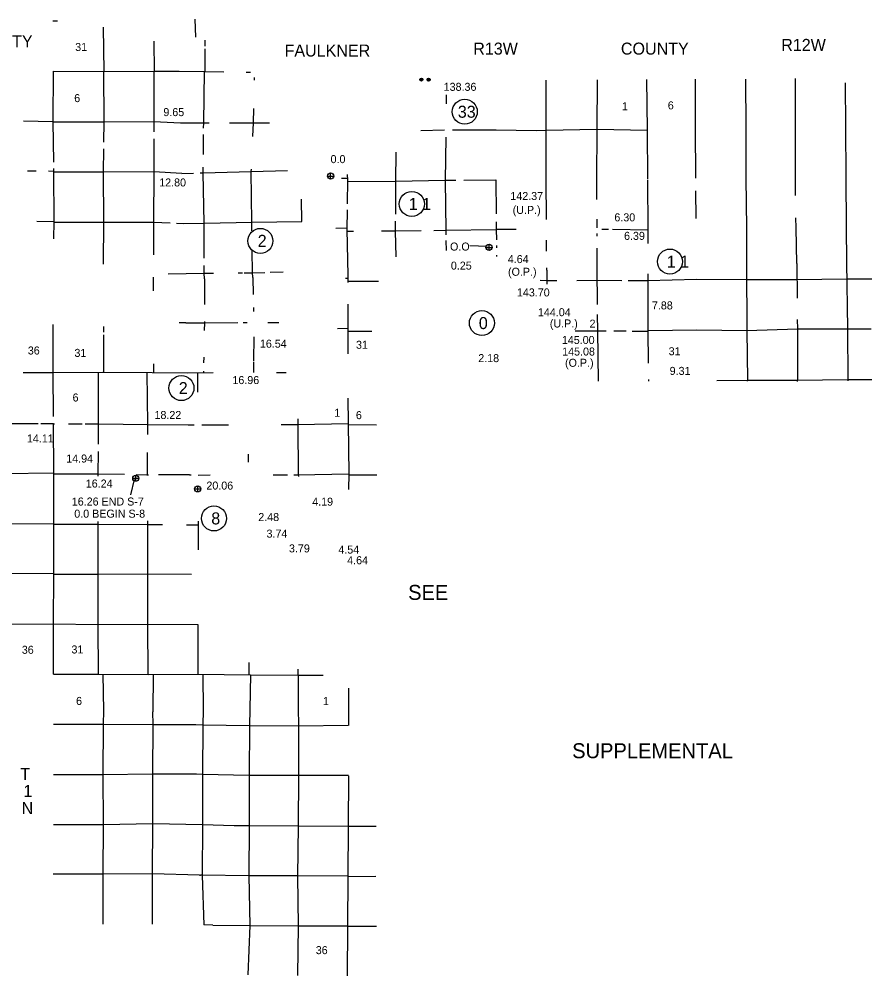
# Model space of a CAD drawing. Extents: x 1127717 to 1741049, y 2026793 to 2244711.
# Drawn here: x 1147166 to 1169656, y 2120572 to 2145808 of the extents above; entities that cross this region are included whole.
import ezdxf

# ---------------------------------------------------------------- set-up
doc = ezdxf.new("R2010")
doc.units = 0
for name, color, linetype in [('25', 7, 'Continuous'), ('26', 7, 'Continuous'), ('27', 7, 'Continuous'), ('30', 7, 'Continuous'), ('4', 7, 'Continuous'), ('5', 7, 'Continuous'), ('58', 7, 'Continuous')]:
    doc.layers.add(name, color=color, linetype=linetype)

msp = doc.modelspace()

# ---------------------------------------------------------------- linework, layer by layer
at = {"layer": '25'}
for p, q in [((1159050, 2139833), (1159511, 2139820)), ((1150109, 2133259), (1150210, 2133664))]:
    msp.add_line(p, q, dxfattribs=at)
at = {"layer": '26'}
for p, q in [((1157736, 2144214), (1157817, 2144214)), ((1157776, 2144173), (1157776, 2144255)), ((1157925, 2144212), (1158006, 2144212)), ((1157965, 2144171), (1157965, 2144253)), ((1155382, 2141589), (1155382, 2141751)), ((1155301, 2141670), (1155463, 2141670)), ((1159478, 2139788), (1159640, 2139788)), ((1159559, 2139707), (1159559, 2139870)), ((1150161, 2133698), (1150324, 2133698)), ((1150242, 2133617), (1150242, 2133780)), ((1151795, 2133418), (1151957, 2133418)), ((1151876, 2133336), (1151876, 2133499))]:
    msp.add_line(p, q, dxfattribs=at)
for centre, radius in [((1157776, 2144214), 40.6), ((1157965, 2144212), 40.6), ((1155382, 2141670), 81.2), ((1159559, 2139788), 81.2), ((1150242, 2133698), 81.2), ((1151876, 2133418), 81.2)]:
    msp.add_circle(centre, radius, dxfattribs=at)
at = {"layer": '27'}
for centre in [(1158919, 2143366), (1157523, 2140933), (1153529, 2139959), (1164330, 2139413), (1159371, 2137791), (1151447, 2136076), (1152305, 2132638)]:
    msp.add_circle(centre, 330, dxfattribs=at)
at = {"layer": '4'}
for points in [[(1148062, 2144437), (1148059, 2143103), (1148069, 2142036)], [(1148062, 2144437), (1149389, 2144429), (1150724, 2144435), (1151390, 2144439)], [(1151390, 2144439), (1152067, 2144425), (1152561, 2144419)], [(1153154, 2144411), (1153266, 2144410)], [(1163748, 2141591), (1163736, 2142886), (1163725, 2144214)], [(1148070, 2141867), (1148071, 2141785), (1148078, 2140471), (1148072, 2140012)], [(1155821, 2141714), (1155825, 2141571), (1155816, 2140932)], [(1163753, 2139887), (1163754, 2140255), (1163747, 2141558)], [(1155814, 2140774), (1155806, 2140259), (1155831, 2139056)], [(1155832, 2139054), (1155831, 2139056)], [(1155832, 2139054), (1155832, 2138860)], [(1163751, 2139092), (1163748, 2137602), (1163757, 2136730)], [(1155834, 2138286), (1155835, 2137650), (1155836, 2136977)], [(1148070, 2135328), (1148066, 2136495), (1148063, 2137755)], [(1147277, 2136487), (1148070, 2136490), (1149358, 2136492), (1150678, 2136488), (1151594, 2136481)], [(1151594, 2136481), (1152287, 2136483)], [(1153953, 2136488), (1154205, 2136488)], [(1163761, 2136303), (1163761, 2136270), (1163761, 2136255)], [(1165563, 2136280), (1166367, 2136281), (1167690, 2136288), (1169019, 2136302), (1169653, 2136305)], [(1155838, 2135813), (1155858, 2133813), (1155856, 2133403)], [(1148071, 2128532), (1148077, 2129859), (1148082, 2131177), (1148082, 2132492), (1148078, 2133850), (1148071, 2135146)], [(1148071, 2128532), (1149248, 2128528), (1150580, 2128525), (1151876, 2128532)], [(1151876, 2128532), (1153266, 2128514), (1154528, 2128501), (1155183, 2128505)], [(1155852, 2128165), (1155849, 2127175)], [(1155852, 2125851), (1155845, 2124523), (1155835, 2123190), (1155828, 2121885), (1155819, 2120572)]]:
    msp.add_lwpolyline(points, dxfattribs=at)
at = {"layer": '5'}
for points in [[(1151803, 2145808), (1151814, 2145330)], [(1148052, 2145759), (1148182, 2145759)], [(1149380, 2145593), (1149396, 2144429)], [(1150718, 2145227), (1150730, 2144435)], [(1152076, 2144425), (1152074, 2145022)], [(1152076, 2145097), (1152076, 2145250)], [(1149390, 2144429), (1149397, 2143102), (1149390, 2142560)], [(1150722, 2144435), (1150719, 2143104), (1150719, 2142835)], [(1152033, 2142935), (1152034, 2143076), (1152058, 2144425)], [(1153370, 2144196), (1153371, 2144268)], [(1161074, 2140522), (1161065, 2141570), (1161067, 2142874), (1161070, 2144199)], [(1162413, 2144208), (1162402, 2142898), (1162390, 2141575), (1162395, 2141053)], [(1165012, 2141613), (1165001, 2142941), (1165008, 2144222)], [(1166325, 2144226), (1166330, 2142949), (1166331, 2141616), (1166351, 2140295), (1166353, 2139328)], [(1167646, 2141158), (1167640, 2141620), (1167641, 2142957), (1167638, 2144238)], [(1168956, 2144127), (1168959, 2142963), (1168973, 2141645), (1168982, 2140319), (1168990, 2139397)], [(1158426, 2143808), (1158425, 2143578)], [(1153331, 2142715), (1153347, 2143071), (1153355, 2143455)], [(1147284, 2143122), (1148059, 2143112)], [(1148059, 2143101), (1149395, 2143103), (1150719, 2143105), (1151426, 2143077)], [(1151426, 2143077), (1152033, 2143074), (1152175, 2143073)], [(1152717, 2143072), (1153347, 2143070), (1153767, 2143071)], [(1152027, 2142241), (1152031, 2142768)], [(1158382, 2142876), (1157764, 2142864)], [(1160799, 2142866), (1159743, 2142879), (1158594, 2142878)], [(1163736, 2142868), (1162401, 2142897), (1161065, 2142872), (1160799, 2142866)], [(1150719, 2142652), (1150718, 2141779), (1150714, 2140456), (1150708, 2139591)], [(1158422, 2142695), (1158404, 2141555), (1158418, 2140235)], [(1149388, 2142391), (1149380, 2141774), (1149395, 2140458), (1149385, 2139347)], [(1157099, 2142297), (1157094, 2141532), (1157089, 2140668)], [(1147616, 2141799), (1147387, 2141802)], [(1148071, 2141792), (1147937, 2141794)], [(1151458, 2141739), (1150716, 2141778), (1149378, 2141773), (1148071, 2141774)], [(1151458, 2141739), (1151763, 2141748)], [(1151940, 2141753), (1152022, 2141755), (1153290, 2141791), (1154243, 2141818)], [(1152047, 2139501), (1152050, 2140430), (1152023, 2141757), (1152024, 2141906)], [(1153305, 2140223), (1153301, 2140451), (1153290, 2141792), (1153292, 2141849)], [(1155672, 2141614), (1155824, 2141616)], [(1155825, 2141529), (1157093, 2141533), (1158404, 2141559), (1158686, 2141560)], [(1158898, 2141561), (1159736, 2141565)], [(1159736, 2141565), (1159746, 2140672)], [(1165019, 2140549), (1165014, 2141280)], [(1154623, 2140473), (1154612, 2141058)], [(1157088, 2140482), (1157086, 2140219), (1157105, 2139535)], [(1162400, 2140530), (1162402, 2140305)], [(1167673, 2139364), (1167658, 2140303), (1167654, 2140565)], [(1147631, 2140477), (1148078, 2140472)], [(1148078, 2140455), (1149394, 2140457), (1150714, 2140457), (1151152, 2140437)], [(1151318, 2140429), (1151502, 2140421)], [(1151502, 2140421), (1152051, 2140430), (1153300, 2140450), (1154619, 2140472)], [(1155523, 2140297), (1155807, 2140301)], [(1156722, 2140220), (1157087, 2140221), (1157770, 2140230)], [(1158100, 2140234), (1158419, 2140238), (1159751, 2140257)], [(1158418, 2140235), (1158420, 2140122)], [(1159748, 2140463), (1159750, 2140256), (1159754, 2139985)], [(1160278, 2140255), (1159751, 2140257)], [(1162710, 2140258), (1162532, 2140261)], [(1163754, 2140241), (1162819, 2140257)], [(1155807, 2140219), (1155982, 2140219)], [(1161078, 2139688), (1161077, 2139977)], [(1162402, 2140153), (1162402, 2140084)], [(1158423, 2139967), (1158428, 2139705)], [(1159756, 2139836), (1159757, 2139775)], [(1162403, 2139766), (1162403, 2139223)], [(1153330, 2138989), (1153324, 2139121), (1153314, 2139708)], [(1159759, 2139584), (1159760, 2139550)], [(1152053, 2138956), (1152046, 2139104), (1152047, 2139306)], [(1161080, 2139189), (1161080, 2139248)], [(1162403, 2139223), (1162412, 2138279)], [(1166353, 2139328), (1166360, 2137592), (1166374, 2136283)], [(1167673, 2139364), (1167683, 2138445)], [(1168990, 2139397), (1169011, 2137636), (1169019, 2136301), (1169019, 2136264)], [(1150704, 2139001), (1150703, 2138924)], [(1151094, 2139090), (1152047, 2139104), (1152293, 2139107)], [(1152941, 2139114), (1153056, 2139116)], [(1153103, 2139118), (1153325, 2139120), (1153645, 2139127)], [(1153330, 2138989), (1153340, 2138548)], [(1153785, 2139130), (1154134, 2139139)], [(1155832, 2138968), (1155777, 2138967)], [(1161080, 2139189), (1161081, 2138818)], [(1150703, 2138924), (1150705, 2138640)], [(1152053, 2138956), (1152052, 2138284)], [(1155832, 2138895), (1156648, 2138897)], [(1160911, 2138922), (1161080, 2138914), (1161350, 2138915)], [(1161872, 2138917), (1162403, 2138919), (1163064, 2138917)], [(1163227, 2138917), (1163745, 2138915), (1165031, 2138953), (1166354, 2138943), (1167676, 2138944), (1168996, 2138955), (1169656, 2138955)], [(1153348, 2138201), (1153350, 2138096)], [(1162415, 2138021), (1162419, 2137588), (1162439, 2136255)], [(1151560, 2137797), (1151387, 2137801)], [(1151560, 2137797), (1152051, 2137800), (1152932, 2137804)], [(1152051, 2137835), (1152051, 2137800), (1152047, 2137591)], [(1153071, 2137805), (1153179, 2137805)], [(1153723, 2137807), (1154013, 2137807)], [(1167689, 2137883), (1167692, 2137641), (1167698, 2136288)], [(1149391, 2137698), (1149391, 2137555)], [(1149391, 2137480), (1149395, 2136492)], [(1155563, 2137652), (1155834, 2137653)], [(1155835, 2137574), (1156468, 2137575)], [(1161829, 2137587), (1162418, 2137588), (1162651, 2137586)], [(1162855, 2137585), (1163180, 2137582)], [(1163331, 2137581), (1163751, 2137578)], [(1163752, 2137599), (1165037, 2137611), (1165698, 2137602), (1166361, 2137592), (1167692, 2137639), (1169011, 2137637), (1169641, 2137636)], [(1153353, 2137429), (1153347, 2136796)], [(1150709, 2136719), (1150709, 2136487)], [(1152035, 2136892), (1152033, 2136744)], [(1153347, 2136767), (1153344, 2136486)], [(1149251, 2136492), (1149249, 2135128), (1149247, 2134597)], [(1150558, 2134855), (1150560, 2135119), (1150544, 2136488)], [(1151867, 2136480), (1151871, 2135970)], [(1152029, 2136526), (1152028, 2136482)], [(1166366, 2136282), (1166366, 2136258)], [(1167690, 2136287), (1167690, 2136252)], [(1142244, 2135187), (1142789, 2135183), (1144105, 2135213), (1145455, 2135165), (1146764, 2135145), (1147667, 2135144)], [(1154519, 2135267), (1154520, 2135114), (1154529, 2133792), (1154530, 2133745)], [(1147736, 2135144), (1148071, 2135143)], [(1148071, 2135129), (1148101, 2135129)], [(1148467, 2135129), (1148825, 2135129)], [(1148912, 2135129), (1149255, 2135130), (1150565, 2135117), (1151628, 2135107)], [(1151628, 2135107), (1151786, 2135109)], [(1151984, 2135109), (1152684, 2135109)], [(1154074, 2135112), (1154520, 2135114), (1155845, 2135140)], [(1155847, 2135113), (1156590, 2135108)], [(1149247, 2134403), (1149245, 2133810), (1149245, 2133750)], [(1150550, 2133771), (1150550, 2133785), (1150555, 2134379)], [(1153204, 2134336), (1153204, 2134118)], [(1148078, 2133834), (1146733, 2133815), (1145435, 2133830), (1144103, 2133844), (1142788, 2133856), (1142277, 2133862)], [(1149948, 2133796), (1149245, 2133810), (1148078, 2133810)], [(1150579, 2133783), (1150550, 2133783), (1150256, 2133789)], [(1151659, 2133785), (1150842, 2133784)], [(1151659, 2133785), (1151706, 2133784)], [(1151885, 2133782), (1152205, 2133784)], [(1153863, 2133791), (1154241, 2133792)], [(1154412, 2133792), (1154529, 2133792), (1155857, 2133813)], [(1155857, 2133790), (1156596, 2133787)], [(1142306, 2132533), (1142789, 2132537), (1144104, 2132515), (1145423, 2132499), (1146747, 2132495), (1148082, 2132501)], [(1148082, 2132483), (1149243, 2132483), (1150561, 2132480), (1150948, 2132477)], [(1149242, 2132557), (1149241, 2132484), (1149241, 2131158), (1149239, 2129842), (1149247, 2128528)], [(1150568, 2128525), (1150561, 2129852), (1150563, 2131172), (1150557, 2132480), (1150557, 2132573)], [(1151580, 2132472), (1151692, 2132471)], [(1151692, 2132471), (1151887, 2132471)], [(1151887, 2132570), (1151886, 2131813)], [(1148082, 2131187), (1146745, 2131173), (1145426, 2131180), (1144105, 2131195), (1142783, 2131203), (1142338, 2131205)], [(1151716, 2131162), (1150561, 2131171), (1149239, 2131161), (1148082, 2131162)], [(1142370, 2129895), (1142795, 2129891), (1144110, 2129870), (1145431, 2129867), (1146756, 2129849), (1148077, 2129861)], [(1148077, 2129854), (1149239, 2129843), (1150563, 2129852), (1151877, 2129844)], [(1151877, 2129844), (1151878, 2128533)], [(1153221, 2128840), (1153225, 2128515)], [(1154517, 2128660), (1154516, 2128500)], [(1149373, 2128528), (1149389, 2127559)], [(1150697, 2128526), (1150691, 2127540)], [(1152012, 2128528), (1152017, 2127573)], [(1153268, 2128515), (1153254, 2127606)], [(1154526, 2128499), (1154529, 2127640)], [(1154529, 2127640), (1154534, 2127171), (1154533, 2125858), (1154524, 2124530), (1154511, 2123203), (1154525, 2121895), (1154512, 2120584)], [(1149389, 2127559), (1149384, 2127212), (1149370, 2125880), (1149380, 2124564), (1149376, 2123251), (1149375, 2121932)], [(1150683, 2121933), (1150685, 2123264), (1150691, 2124593), (1150694, 2125891), (1150698, 2127205), (1150691, 2127540)], [(1152017, 2127573), (1152011, 2127194), (1152005, 2125883), (1152005, 2124560), (1151991, 2123223), (1152034, 2121917)], [(1153254, 2127606), (1153245, 2127180), (1153236, 2125860), (1153230, 2124537), (1153226, 2123212), (1153248, 2121898), (1153194, 2120596)], [(1148076, 2127210), (1149385, 2127212), (1150699, 2127205), (1151823, 2127202)], [(1151823, 2127202), (1152012, 2127195), (1153246, 2127180), (1154534, 2127171), (1155846, 2127186)], [(1151844, 2125890), (1150695, 2125892), (1149369, 2125879), (1148072, 2125879)], [(1155851, 2125857), (1154528, 2125856), (1153232, 2125859), (1152001, 2125882), (1151844, 2125890)], [(1148071, 2124564), (1149380, 2124564), (1150692, 2124593), (1152005, 2124563)], [(1152005, 2124563), (1152837, 2124543)], [(1152837, 2124543), (1153229, 2124535), (1154526, 2124530), (1155847, 2124523), (1156586, 2124518)], [(1151921, 2123230), (1150684, 2123264), (1149375, 2123252), (1148064, 2123254)], [(1151921, 2123230), (1151951, 2123228)], [(1155835, 2123198), (1154507, 2123207), (1153221, 2123214), (1151988, 2123225), (1151951, 2123228)], [(1156576, 2123193), (1155835, 2123187)], [(1152276, 2121914), (1152034, 2121917)], [(1152276, 2121914), (1153247, 2121900), (1154525, 2121896), (1155828, 2121891)], [(1155828, 2121882), (1156589, 2121884)]]:
    msp.add_lwpolyline(points, dxfattribs=at)

# ---------------------------------------------------------------- texts
at = {"layer": '25'}
for s, p in [('138.36', (1158363, 2143917)), ('0.0', (1155380, 2142010)), ('O.O', (1158531, 2139703)), ('20.06', (1152105, 2133399)), ('16.26 END S-7', (1148555, 2132978)), ('0.0 BEGIN S-8', (1148621, 2132658))]:
    msp.add_text(s, height=211.2, dxfattribs=at).set_placement(p)
at = {"layer": '27'}
for s, height, p in [('33', 316.8, (1158736, 2143207)), ('1 1', 316.8, (1157441, 2140775)), ('2', 317, (1153458, 2139801)), ('1 1', 316.8, (1164247, 2139254)), ('0', 317, (1159290, 2137633)), ('2', 317, (1151376, 2135918)), ('8', 317, (1152234, 2132480))]:
    msp.add_text(s, height=height, dxfattribs=at).set_placement(p)
at = {"layer": '30'}
for s, height, p in [('COUNTY', 316.8, (1145734, 2145068)), ('R12W', 316.8, (1167265, 2144970)), ('FAULKNER', 316.8, (1154166, 2144822)), ('R13W', 316.8, (1159143, 2144872)), ('COUNTY', 316.8, (1163037, 2144872)), ('SEE', 396, (1157426, 2130489)), ('SUPPLEMENTAL', 396, (1161752, 2126313)), ('T', 317, (1147198, 2125741)), ('1', 317, (1147279, 2125291)), ('N', 317, (1147230, 2124840))]:
    msp.add_text(s, height=height, dxfattribs=at).set_placement(p)
at = {"layer": '5'}
for s, height, p in [('31', 211.2, (1148645, 2144968)), ('6', 211, (1148619, 2143619)), ('1', 211, (1163064, 2143405)), ('6', 211, (1164274, 2143428)), ('31', 211.2, (1156051, 2137113)), ('36', 211.2, (1147395, 2136962)), ('31', 211.2, (1148625, 2136899)), ('31', 211.2, (1164296, 2136942)), ('6', 211, (1148576, 2135722)), ('1', 211, (1155478, 2135320)), ('6', 211, (1156048, 2135257)), ('36', 211.2, (1147237, 2129068)), ('31', 211.2, (1148546, 2129076)), ('6', 211, (1148668, 2127719)), ('1', 211, (1155178, 2127716)), ('36', 211.2, (1154989, 2121145))]:
    msp.add_text(s, height=height, dxfattribs=at).set_placement(p)
at = {"layer": '58'}
for s, height, p in [('9.65', 211.2, (1150970, 2143250)), ('12.80', 211.2, (1150861, 2141395)), ('142.37', 211.2, (1160121, 2141037)), ('(U.P.)', 211.2, (1160183, 2140670)), ('6.30', 211.2, (1162865, 2140474)), ('6.39', 211.2, (1163120, 2139986)), ('4.64', 211.2, (1160054, 2139374)), ('0.25', 211.2, (1158553, 2139201)), ('(O.P.)', 211.2, (1160060, 2139039)), ('143.70', 211.2, (1160295, 2138494)), ('7.88', 211.2, (1163855, 2138151)), ('144.04', 211.2, (1160849, 2137972)), ('(U.P.)', 211.2, (1161162, 2137675)), ('2', 211, (1162210, 2137671)), ('145.00', 211.2, (1161480, 2137239)), ('16.54', 211.2, (1153516, 2137142)), ('2.18', 211.2, (1159275, 2136761)), ('145.08', 211.2, (1161488, 2136935)), ('(O.P.)', 211.2, (1161564, 2136638)), ('9.31', 211.2, (1164323, 2136424)), ('16.96', 211.2, (1152791, 2136182)), ('18.22', 211.2, (1150736, 2135262)), ('14.11', 211.2, (1147372, 2134642)), ('14.94', 211.2, (1148409, 2134113)), ('16.24', 211.2, (1148924, 2133453)), ('4.19', 211.2, (1154896, 2132974)), ('2.48', 211.2, (1153473, 2132569)), ('3.74', 211.2, (1153691, 2132132)), ('3.79', 211.2, (1154283, 2131742)), ('4.54', 211.2, (1155585, 2131711)), ('4.64', 211.2, (1155818, 2131430))]:
    msp.add_text(s, height=height, dxfattribs=at).set_placement(p)

doc.saveas('drawing.dxf')
